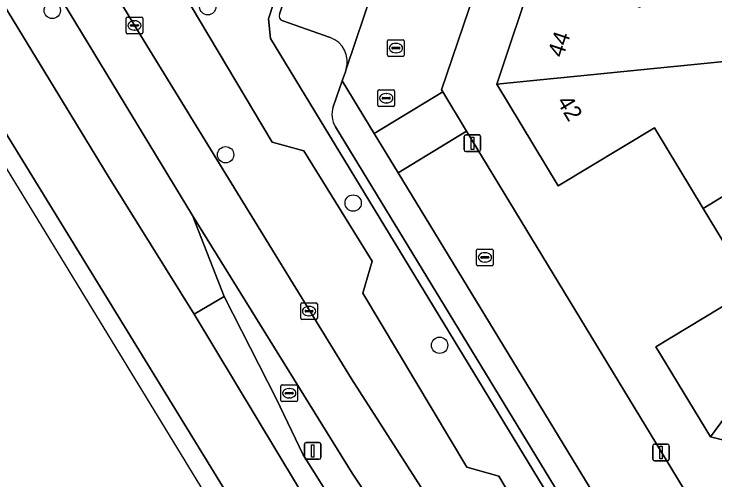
# Model space of a CAD drawing. Extents: x 157767 to 159172, y 387839 to 389425.
# Drawn here: x 158168.15 to 158210.24, y 388273.19 to 388301.19 of the extents above; entities that cross this region are included whole.
import ezdxf

# ---------------------------------------------------------------- set-up
doc = ezdxf.new("R2010")
doc.units = 0
for name, color, linetype in [('IMGEO_Berm_groen', 7, 'Continuous'), ('IMGEO_Boom', 7, 'Continuous'), ('IMGEO_Erf', 7, 'Continuous'), ('IMGEO_Fietspad_gesloten', 7, 'Continuous'), ('IMGEO_Groenvoorziening', 7, 'Continuous'), ('IMGEO_Kolk', 7, 'Continuous'), ('IMGEO_Lichtmast', 7, 'Continuous'), ('IMGEO_Muur', 7, 'Continuous'), ('IMGEO_Pand', 7, 'Continuous'), ('IMGEO_Pand_nummerreeks', 7, 'Continuous'), ('IMGEO_Parkeervlak_open', 7, 'Continuous'), ('IMGEO_Rijbaan_lokaal_gesloten', 7, 'Continuous'), ('IMGEO_Rijbaan_lokaal_open', 7, 'Continuous'), ('IMGEO_Rijbaan_regionaal_gesloten', 7, 'Continuous'), ('IMGEO_Rioolput', 7, 'Continuous'), ('IMGEO_Voetpad_open', 7, 'Continuous')]:
    doc.layers.add(name, color=color, linetype=linetype)

msp = doc.modelspace()

# ---------------------------------------------------------------- linework, layer by layer
at = {"layer": 'IMGEO_Berm_groen'}
for points in [[(158153.286, 388331.356), (158142.759, 388349.282), (158132.45, 388366.885), (158129.845, 388365.121), (158139.769, 388348), (158157.789, 388317.741), (158173.795, 388291.448), (158178.959, 388283.153), (158180.756, 388284.205), (158178.868, 388289.086), (158165.181, 388311.658)], [(158188.453, 388273.59), (158178.868, 388289.086), (158180.756, 388284.205), (158183.89, 388278.093), (158185.5, 388274.694), (158192.028, 388264.32), (158199.34, 388257.164)]]:
    msp.add_lwpolyline(points, close=True, dxfattribs=at)
at = {"layer": 'IMGEO_Boom'}
for centre in [(158179.783, 388301.621), (158170.443, 388301.401), (158180.854, 388292.73), (158188.512, 388289.829), (158193.701, 388281.281)]:
    msp.add_circle(centre, 0.489, dxfattribs=at)
at = {"layer": 'IMGEO_Erf'}
for points in [[(158207.176, 388335.906), (158193.823, 388296.623), (158193.889, 388296.514), (158195.326, 388294.145), (158209.967, 388270.003), (158232.576, 388264.595), (158245.92, 388272.734), (158246.797, 388271.528), (158258.673, 388278.755)], [(158216.219, 388274.228), (158209.965, 388275.772), (158206.695, 388281.193), (158212.453, 388284.667), (158209.534, 388289.505), (158206.613, 388294.346), (158200.824, 388290.854), (158197.134, 388296.971), (158199.379, 388303.704)]]:
    msp.add_lwpolyline(points, dxfattribs=at)
at = {"layer": 'IMGEO_Fietspad_gesloten'}
msp.add_lwpolyline([(158175.742, 388299.912), (158162.359, 388321.986), (158152.031, 388339.346), (158134.936, 388368.569), (158132.45, 388366.885), (158142.759, 388349.282), (158153.286, 388331.356), (158165.181, 388311.658), (158178.868, 388289.086), (158188.453, 388273.59), (158199.34, 388257.164), (158201.801, 388253.451), (158204.172, 388250), (158207.773, 388244.758), (158210.203, 388246.361), (158201.818, 388258.573), (158195.13, 388268.765), (158188.418, 388279.263)], close=True, dxfattribs=at)
at = {"layer": 'IMGEO_Groenvoorziening'}
msp.add_lwpolyline([(158162.359, 388321.986), (158175.742, 388299.912), (158188.418, 388279.263), (158195.13, 388268.765), (158198.647, 388271.084), (158197.254, 388273.407), (158195.332, 388273.955), (158189.095, 388284.416), (158189.658, 388286.335), (158185.543, 388292.972), (158183.658, 388293.483), (158173.351, 388310.787), (158171.296, 388314.237), (158171.855, 388316.141), (158165.73, 388326.242)], dxfattribs=at)
msp.add_lwpolyline([(158204.079, 388265.917), (158183.553, 388299.72), (158183.422, 388300.898), (158186.634, 388310.76), (158179.922, 388313.047), (158175.446, 388314.592), (158173.351, 388310.787), (158183.658, 388293.483), (158185.543, 388292.972), (158189.658, 388286.335), (158189.095, 388284.416), (158195.332, 388273.955), (158197.254, 388273.407), (158198.647, 388271.084), (158207.528, 388256.281), (158219.17, 388253.347), (158226.854, 388257.889), (158227.06, 388260.07), (158226.561, 388260.197)], close=True, dxfattribs=at)
at = {"layer": 'IMGEO_Kolk'}
for p, q in [((158174.881, 388300.076), (158174.881, 388300.928)), ((158174.956, 388301.002), (158175.808, 388301.002)), ((158175.369, 388300.782), (158175.394, 388300.782)), ((158175.882, 388300.928), (158175.882, 388300.076)), ((158175.14, 388300.496), (158175.14, 388300.508)), ((158175.578, 388300.459), (158175.18, 388300.459)), ((158175.183, 388300.545), (158175.581, 388300.545)), ((158175.624, 388300.508), (158175.624, 388300.496)), ((158175.808, 388300.002), (158174.956, 388300.002)), ((158175.392, 388300.222), (158175.367, 388300.222)), ((158190.579, 388298.716), (158190.579, 388299.568)), ((158190.654, 388299.642), (158191.506, 388299.642)), ((158191.067, 388299.422), (158191.092, 388299.422)), ((158191.58, 388299.568), (158191.58, 388298.716)), ((158190.838, 388299.136), (158190.838, 388299.148)), ((158191.276, 388299.099), (158190.878, 388299.099)), ((158190.881, 388299.185), (158191.279, 388299.185)), ((158191.322, 388299.148), (158191.322, 388299.136)), ((158191.506, 388298.642), (158190.654, 388298.642)), ((158191.09, 388298.862), (158191.065, 388298.862)), ((158195.921, 388286.138), (158195.921, 388286.99)), ((158195.996, 388287.064), (158196.848, 388287.064)), ((158196.409, 388286.844), (158196.434, 388286.844)), ((158196.922, 388286.99), (158196.922, 388286.138)), ((158196.18, 388286.558), (158196.18, 388286.57)), ((158196.618, 388286.521), (158196.22, 388286.521)), ((158196.223, 388286.607), (158196.621, 388286.607)), ((158196.664, 388286.57), (158196.664, 388286.558)), ((158196.848, 388286.064), (158195.996, 388286.064)), ((158196.432, 388286.284), (158196.407, 388286.284)), ((158185.436, 388283.833), (158186.288, 388283.833)), ((158185.361, 388282.907), (158185.361, 388283.759)), ((158185.849, 388283.613), (158185.874, 388283.613)), ((158186.362, 388283.759), (158186.362, 388282.907)), ((158185.62, 388283.327), (158185.62, 388283.339)), ((158186.058, 388283.29), (158185.66, 388283.29)), ((158185.663, 388283.376), (158186.061, 388283.376)), ((158185.872, 388283.053), (158185.847, 388283.053)), ((158186.104, 388283.339), (158186.104, 388283.327)), ((158186.288, 388282.833), (158185.436, 388282.833))]:
    msp.add_line(p, q, dxfattribs=at)
for points in [[(158174.881, 388300.076), (158174.881, 388300.928)], [(158174.956, 388301.002), (158175.808, 388301.002)], [(158175.882, 388300.928), (158175.882, 388300.076)], [(158175.808, 388300.002), (158174.956, 388300.002)], [(158190.579, 388298.716), (158190.579, 388299.568)], [(158190.654, 388299.642), (158191.506, 388299.642)], [(158191.58, 388299.568), (158191.58, 388298.716)], [(158191.506, 388298.642), (158190.654, 388298.642)], [(158195.921, 388286.138), (158195.921, 388286.99)], [(158195.996, 388287.064), (158196.848, 388287.064)], [(158196.922, 388286.99), (158196.922, 388286.138)], [(158196.848, 388286.064), (158195.996, 388286.064)], [(158185.436, 388283.833), (158186.288, 388283.833)], [(158185.361, 388282.907), (158185.361, 388283.759)], [(158186.362, 388283.759), (158186.362, 388282.907)], [(158186.288, 388282.833), (158185.436, 388282.833)]]:
    msp.add_lwpolyline(points, dxfattribs=at)
for centre, radius, start, end in [((158174.958, 388300.926), 0.0765, 91.552, 178.448), ((158174.958, 388300.926), 0.0765, 91.552, 178.448), ((158175.806, 388300.926), 0.0765, 1.552, 88.448), ((158175.806, 388300.926), 0.0765, 1.552, 88.448), ((158175.18, 388300.505), 0.0403, 85.8775, 175.7526), ((158175.177, 388300.495), 0.0366, 178.938, 274.7102), ((158175.581, 388300.502), 0.043, 264.8664, 352.4533), ((158175.585, 388300.507), 0.0386, 1.7309, 96.639), ((158174.958, 388300.078), 0.0765, 181.552, 268.448), ((158174.958, 388300.078), 0.0765, 181.552, 268.448), ((158175.806, 388300.078), 0.0765, 271.552, 358.448), ((158175.806, 388300.078), 0.0765, 271.552, 358.448), ((158190.656, 388299.566), 0.0765, 91.552, 178.448), ((158190.656, 388299.566), 0.0765, 91.552, 178.448), ((158191.504, 388299.566), 0.0765, 1.552, 88.448), ((158191.504, 388299.566), 0.0765, 1.552, 88.448), ((158190.878, 388299.145), 0.0403, 85.8775, 175.7526), ((158190.875, 388299.135), 0.0366, 178.938, 274.7102), ((158191.279, 388299.142), 0.043, 264.8664, 352.4533), ((158191.283, 388299.147), 0.0386, 1.7309, 96.639), ((158190.656, 388298.718), 0.0765, 181.552, 268.448), ((158190.656, 388298.718), 0.0765, 181.552, 268.448), ((158191.504, 388298.718), 0.0765, 271.552, 358.448), ((158191.504, 388298.718), 0.0765, 271.552, 358.448), ((158195.998, 388286.988), 0.0765, 91.552, 178.448), ((158195.998, 388286.988), 0.0765, 91.552, 178.448), ((158196.846, 388286.988), 0.0765, 1.552, 88.448), ((158196.846, 388286.988), 0.0765, 1.552, 88.448), ((158196.22, 388286.567), 0.0403, 85.8775, 175.7526), ((158196.217, 388286.557), 0.0366, 178.938, 274.7102), ((158196.621, 388286.564), 0.043, 264.8664, 352.4533), ((158196.625, 388286.569), 0.0386, 1.7309, 96.639), ((158195.998, 388286.14), 0.0765, 181.552, 268.448), ((158195.998, 388286.14), 0.0765, 181.552, 268.448), ((158196.846, 388286.14), 0.0765, 271.552, 358.448), ((158196.846, 388286.14), 0.0765, 271.552, 358.448), ((158185.438, 388283.757), 0.0765, 91.552, 178.448), ((158185.438, 388283.757), 0.0765, 91.552, 178.448), ((158186.286, 388283.757), 0.0765, 1.552, 88.448), ((158186.286, 388283.757), 0.0765, 1.552, 88.448), ((158185.66, 388283.336), 0.0403, 85.8775, 175.7526), ((158185.657, 388283.326), 0.0366, 178.938, 274.7102), ((158186.061, 388283.333), 0.043, 264.8664, 352.4533), ((158186.065, 388283.338), 0.0386, 1.7309, 96.639), ((158185.438, 388282.909), 0.0765, 181.552, 268.448), ((158185.438, 388282.909), 0.0765, 181.552, 268.448), ((158186.286, 388282.909), 0.0765, 271.552, 358.448), ((158186.286, 388282.909), 0.0765, 271.552, 358.448)]:
    msp.add_arc(centre, radius, start, end, dxfattribs=at)
for centre, major_axis, ratio, start_param, end_param in [((158175.368, 388300.502), (-0.387, 0.002), 0.722429, 4.712389, 7.853982), ((158175.393, 388300.502), (-0.39, 0.002), 0.717154, 1.570796, 4.712389), ((158191.066, 388299.142), (-0.387, 0.002), 0.722429, 4.712389, 7.853982), ((158191.091, 388299.142), (-0.39, 0.002), 0.717154, 1.570796, 4.712389), ((158196.408, 388286.564), (-0.387, 0.002), 0.722429, 4.712389, 7.853982), ((158196.433, 388286.564), (-0.39, 0.002), 0.717154, 1.570796, 4.712389), ((158185.848, 388283.333), (-0.387, 0.002), 0.722429, 4.712389, 7.853982), ((158185.873, 388283.333), (-0.39, 0.002), 0.717154, 1.570796, 4.712389)]:
    msp.add_ellipse(centre, major_axis=major_axis, ratio=ratio, start_param=start_param, end_param=end_param, dxfattribs=at)
at = {"layer": 'IMGEO_Lichtmast'}
for p, q in [((158195.278, 388293.921), (158196.068, 388293.921)), ((158196.068, 388293.921), (158195.278, 388293.921)), ((158195.178, 388293.021), (158195.178, 388293.821)), ((158195.178, 388293.821), (158195.178, 388293.021)), ((158196.168, 388293.821), (158196.168, 388293.021)), ((158196.168, 388293.021), (158196.168, 388293.821)), ((158196.068, 388292.921), (158195.278, 388292.921)), ((158195.278, 388292.921), (158196.068, 388292.921)), ((158185.69, 388275.431), (158186.48, 388275.431)), ((158186.48, 388275.431), (158185.69, 388275.431)), ((158185.59, 388274.531), (158185.59, 388275.331)), ((158185.59, 388275.331), (158185.59, 388274.531)), ((158186.58, 388275.331), (158186.58, 388274.531)), ((158186.58, 388274.531), (158186.58, 388275.331)), ((158206.501, 388274.44), (158206.501, 388275.24)), ((158206.501, 388275.24), (158206.501, 388274.44)), ((158206.601, 388275.34), (158207.391, 388275.34)), ((158207.391, 388275.34), (158206.601, 388275.34)), ((158207.491, 388275.24), (158207.491, 388274.44)), ((158207.491, 388274.44), (158207.491, 388275.24)), ((158186.48, 388274.431), (158185.69, 388274.431)), ((158185.69, 388274.431), (158186.48, 388274.431)), ((158207.391, 388274.34), (158206.601, 388274.34)), ((158206.601, 388274.34), (158207.391, 388274.34))]:
    msp.add_line(p, q, dxfattribs=at)
for points in [[(158195.598, 388293.796), (158195.748, 388293.796), (158195.748, 388293.046), (158195.598, 388293.046), (158195.598, 388293.796)], [(158186.01, 388275.306), (158186.16, 388275.306), (158186.16, 388274.556), (158186.01, 388274.556), (158186.01, 388275.306)], [(158206.921, 388275.215), (158207.071, 388275.215), (158207.071, 388274.465), (158206.921, 388274.465), (158206.921, 388275.215)]]:
    msp.add_lwpolyline(points, dxfattribs=at)
for centre, start, end in [((158195.278, 388293.821), 90, 180), ((158195.278, 388293.821), 90, 180), ((158196.068, 388293.821), 0, 90), ((158196.068, 388293.821), 360, 90), ((158195.278, 388293.021), 180, 270), ((158195.278, 388293.021), 180, 270), ((158196.068, 388293.021), 270, 0), ((158196.068, 388293.021), 270, 0), ((158185.69, 388275.331), 90, 180), ((158185.69, 388275.331), 90, 180), ((158186.48, 388275.331), 0, 90), ((158186.48, 388275.331), 360, 90), ((158206.601, 388275.24), 90, 180), ((158206.601, 388275.24), 90, 180), ((158207.391, 388275.24), 0, 90), ((158207.391, 388275.24), 360, 90), ((158185.69, 388274.531), 180, 270), ((158185.69, 388274.531), 180, 270), ((158186.48, 388274.531), 270, 0), ((158186.48, 388274.531), 270, 0), ((158206.601, 388274.44), 180, 270), ((158206.601, 388274.44), 180, 270), ((158207.391, 388274.44), 270, 0), ((158207.391, 388274.44), 270, 0)]:
    msp.add_arc(centre, 0.1, start, end, dxfattribs=at)
at = {"layer": 'IMGEO_Muur'}
msp.add_lwpolyline([(158173.351, 388310.787), (158183.658, 388293.483), (158185.543, 388292.972), (158189.658, 388286.335), (158189.095, 388284.416), (158195.332, 388273.955), (158197.254, 388273.407)], dxfattribs=at)
at = {"layer": 'IMGEO_Pand'}
for points in [[(158215.015, 388304.181), (158207.479, 388306.778), (158205.746, 388301.581), (158199.379, 388303.704), (158197.134, 388296.971), (158211.388, 388298.394), (158211.328, 388298.493), (158212.312, 388301.442), (158213.923, 388300.905)], [(158216.235, 388293.601), (158214.392, 388296.656), (158212.958, 388295.791), (158211.388, 388298.394), (158197.134, 388296.971), (158200.824, 388290.854), (158206.613, 388294.346), (158209.534, 388289.505)], [(158216.235, 388293.601), (158209.534, 388289.505), (158212.453, 388284.667), (158206.695, 388281.193), (158209.965, 388275.772), (158218.323, 388287.105), (158216.726, 388289.655), (158218.111, 388290.491)], [(158225.118, 388287.189), (158221.593, 388288.059), (158221.183, 388286.399), (158218.323, 388287.105), (158209.965, 388275.772), (158216.219, 388274.228), (158217.865, 388280.894), (158223.365, 388279.536)]]:
    msp.add_lwpolyline(points, close=True, dxfattribs=at)
at = {"layer": 'IMGEO_Parkeervlak_open'}
for points in [[(158187.003, 388310.002), (158184.081, 388301.187)], [(158188.099, 388297.872), (158191.87, 388309.106)], [(158184.283, 388300.777), (158187.135, 388299.768)], [(158205.034, 388266.328), (158206.891, 388265.879), (158191.218, 388291.646), (158189.778, 388294.013), (158187.857, 388297.171), (158187.319, 388295.617)], [(158187.448, 388294.409), (158204.117, 388266.999)]]:
    msp.add_lwpolyline(points, dxfattribs=at)
for centre, radius, start, end in [((158184.391, 388301.085), 0.326, 161.7384, 250.7189), ((158186.621, 388298.314), 1.542, 343.3559, 70.5452), ((158188.673, 388295.151), 1.432, 160.9945, 211.1963)]:
    msp.add_arc(centre, radius, start, end, dxfattribs=at)
at = {"layer": 'IMGEO_Rijbaan_lokaal_gesloten'}
for points in [[(158197.405, 388255.775), (158192.028, 388264.32), (158185.5, 388274.694), (158183.89, 388278.093), (158180.756, 388284.205), (158178.959, 388283.153)], [(158178.959, 388283.153), (158202.493, 388244.06)]]:
    msp.add_lwpolyline(points, dxfattribs=at)
at = {"layer": 'IMGEO_Rijbaan_lokaal_open'}
msp.add_lwpolyline([(158191.87, 388309.106), (158188.099, 388297.872), (158188.047, 388297.718), (158187.857, 388297.171), (158189.778, 388294.013), (158193.889, 388296.514), (158193.823, 388296.623), (158207.176, 388335.906)], dxfattribs=at)
for points in [[(158189.778, 388294.013), (158191.218, 388291.646), (158195.326, 388294.145), (158193.889, 388296.514)], [(158195.326, 388294.145), (158191.218, 388291.646), (158206.891, 388265.879), (158209.967, 388270.003)]]:
    msp.add_lwpolyline(points, close=True, dxfattribs=at)
at = {"layer": 'IMGEO_Rijbaan_regionaal_gesloten'}
msp.add_lwpolyline([(158127.081, 388358.439), (158199.528, 388239.724), (158200.59, 388240.362), (158192.107, 388254.146), (158166.877, 388295.262), (158150.236, 388322.758), (158131.842, 388353.83), (158117.262, 388378.952), (158097.857, 388412.932), (158070.009, 388461.63), (158044.126, 388506.669), (158040.061, 388513.776), (158019.492, 388549.641), (158005.756, 388573.613), (158005.68, 388573.566), (158005.013, 388573.158), (158051.596, 388490.837), (158089.79, 388423.845), (158099.803, 388406.283)], close=True, dxfattribs=at)
msp.add_lwpolyline([(158131.842, 388353.83), (158150.236, 388322.758), (158166.877, 388295.262), (158192.107, 388254.146), (158200.59, 388240.362), (158203.673, 388242.215), (158202.493, 388244.06), (158178.959, 388283.153), (158173.795, 388291.448), (158157.789, 388317.741), (158139.769, 388348), (158129.845, 388365.121)], dxfattribs=at)
at = {"layer": 'IMGEO_Rioolput'}
for p, q in [((158190, 388295.703), (158190, 388296.555)), ((158190.075, 388296.629), (158190.927, 388296.629)), ((158191.001, 388296.555), (158191.001, 388295.703)), ((158190.259, 388296.123), (158190.259, 388296.135)), ((158190.697, 388296.086), (158190.299, 388296.086)), ((158190.302, 388296.172), (158190.7, 388296.172)), ((158190.488, 388296.409), (158190.513, 388296.409)), ((158190.743, 388296.135), (158190.743, 388296.123)), ((158190.927, 388295.629), (158190.075, 388295.629)), ((158190.511, 388295.849), (158190.486, 388295.849)), ((158184.171, 388277.972), (158184.171, 388278.824)), ((158184.246, 388278.898), (158185.098, 388278.898)), ((158185.172, 388278.824), (158185.172, 388277.972)), ((158184.43, 388278.392), (158184.43, 388278.404)), ((158184.868, 388278.355), (158184.47, 388278.355)), ((158184.473, 388278.441), (158184.871, 388278.441)), ((158184.659, 388278.678), (158184.684, 388278.678)), ((158184.914, 388278.404), (158184.914, 388278.392)), ((158184.682, 388278.118), (158184.657, 388278.118)), ((158185.098, 388277.898), (158184.246, 388277.898))]:
    msp.add_line(p, q, dxfattribs=at)
for points in [[(158190, 388295.703), (158190, 388296.555)], [(158190.075, 388296.629), (158190.927, 388296.629)], [(158191.001, 388296.555), (158191.001, 388295.703)], [(158190.927, 388295.629), (158190.075, 388295.629)], [(158184.171, 388277.972), (158184.171, 388278.824)], [(158184.246, 388278.898), (158185.098, 388278.898)], [(158185.172, 388278.824), (158185.172, 388277.972)], [(158185.098, 388277.898), (158184.246, 388277.898)]]:
    msp.add_lwpolyline(points, dxfattribs=at)
for centre, radius, start, end in [((158190.077, 388296.553), 0.0765, 91.552, 178.448), ((158190.077, 388296.553), 0.0765, 91.552, 178.448), ((158190.925, 388296.553), 0.0765, 1.552, 88.448), ((158190.925, 388296.553), 0.0765, 1.552, 88.448), ((158190.299, 388296.132), 0.0403, 85.8775, 175.7526), ((158190.296, 388296.122), 0.0366, 178.938, 274.7102), ((158190.7, 388296.129), 0.043, 264.8664, 352.4533), ((158190.704, 388296.134), 0.0386, 1.7309, 96.639), ((158190.077, 388295.705), 0.0765, 181.552, 268.448), ((158190.077, 388295.705), 0.0765, 181.552, 268.448), ((158190.925, 388295.705), 0.0765, 271.552, 358.448), ((158190.925, 388295.705), 0.0765, 271.552, 358.448), ((158184.248, 388278.822), 0.0765, 91.552, 178.448), ((158184.248, 388278.822), 0.0765, 91.552, 178.448), ((158185.096, 388278.822), 0.0765, 1.552, 88.448), ((158185.096, 388278.822), 0.0765, 1.552, 88.448), ((158184.47, 388278.401), 0.0403, 85.8775, 175.7526), ((158184.467, 388278.391), 0.0366, 178.938, 274.7102), ((158184.871, 388278.398), 0.043, 264.8664, 352.4533), ((158184.875, 388278.403), 0.0386, 1.7309, 96.639), ((158184.248, 388277.974), 0.0765, 181.552, 268.448), ((158184.248, 388277.974), 0.0765, 181.552, 268.448), ((158185.096, 388277.974), 0.0765, 271.552, 358.448), ((158185.096, 388277.974), 0.0765, 271.552, 358.448)]:
    msp.add_arc(centre, radius, start, end, dxfattribs=at)
for centre, major_axis, ratio, start_param, end_param in [((158190.487, 388296.129), (-0.387, 0.002), 0.722429, 4.712389, 7.853982), ((158190.512, 388296.129), (-0.39, 0.002), 0.717154, 1.570796, 4.712389), ((158184.658, 388278.398), (-0.387, 0.002), 0.722429, 4.712389, 7.853982), ((158184.683, 388278.398), (-0.39, 0.002), 0.717154, 1.570796, 4.712389)]:
    msp.add_ellipse(centre, major_axis=major_axis, ratio=ratio, start_param=start_param, end_param=end_param, dxfattribs=at)
at = {"layer": 'IMGEO_Voetpad_open'}
for points in [[(158187.395, 388310.197), (158186.634, 388310.76), (158183.422, 388300.898), (158183.553, 388299.72), (158204.079, 388265.917), (158226.561, 388260.197), (158227.06, 388260.07), (158229.533, 388259.494), (158229.644, 388260.394), (158208.258, 388265.567), (158206.891, 388265.879), (158205.034, 388266.328)], [(158184.081, 388301.187), (158187.003, 388310.002)], [(158187.135, 388299.768), (158184.283, 388300.777)], [(158187.319, 388295.617), (158187.857, 388297.171), (158188.047, 388297.718), (158188.099, 388297.872)], [(158204.117, 388266.999), (158187.448, 388294.409)]]:
    msp.add_lwpolyline(points, dxfattribs=at)
for centre, radius, start, end in [((158184.391, 388301.085), 0.326, 161.7384, 250.7189), ((158186.621, 388298.314), 1.542, 343.3559, 70.5452), ((158188.673, 388295.151), 1.432, 160.9945, 211.1963)]:
    msp.add_arc(centre, radius, start, end, dxfattribs=at)

# ---------------------------------------------------------------- texts
at = {"layer": 'IMGEO_Pand_nummerreeks'}
for s, rotation, p in [('44', 71.5702, (158201.107, 388298.516)), ('42', 301.0972, (158200.709, 388295.924))]:
    msp.add_text(s, height=1, rotation=rotation, dxfattribs=at).set_placement(p)

doc.saveas('drawing.dxf')
